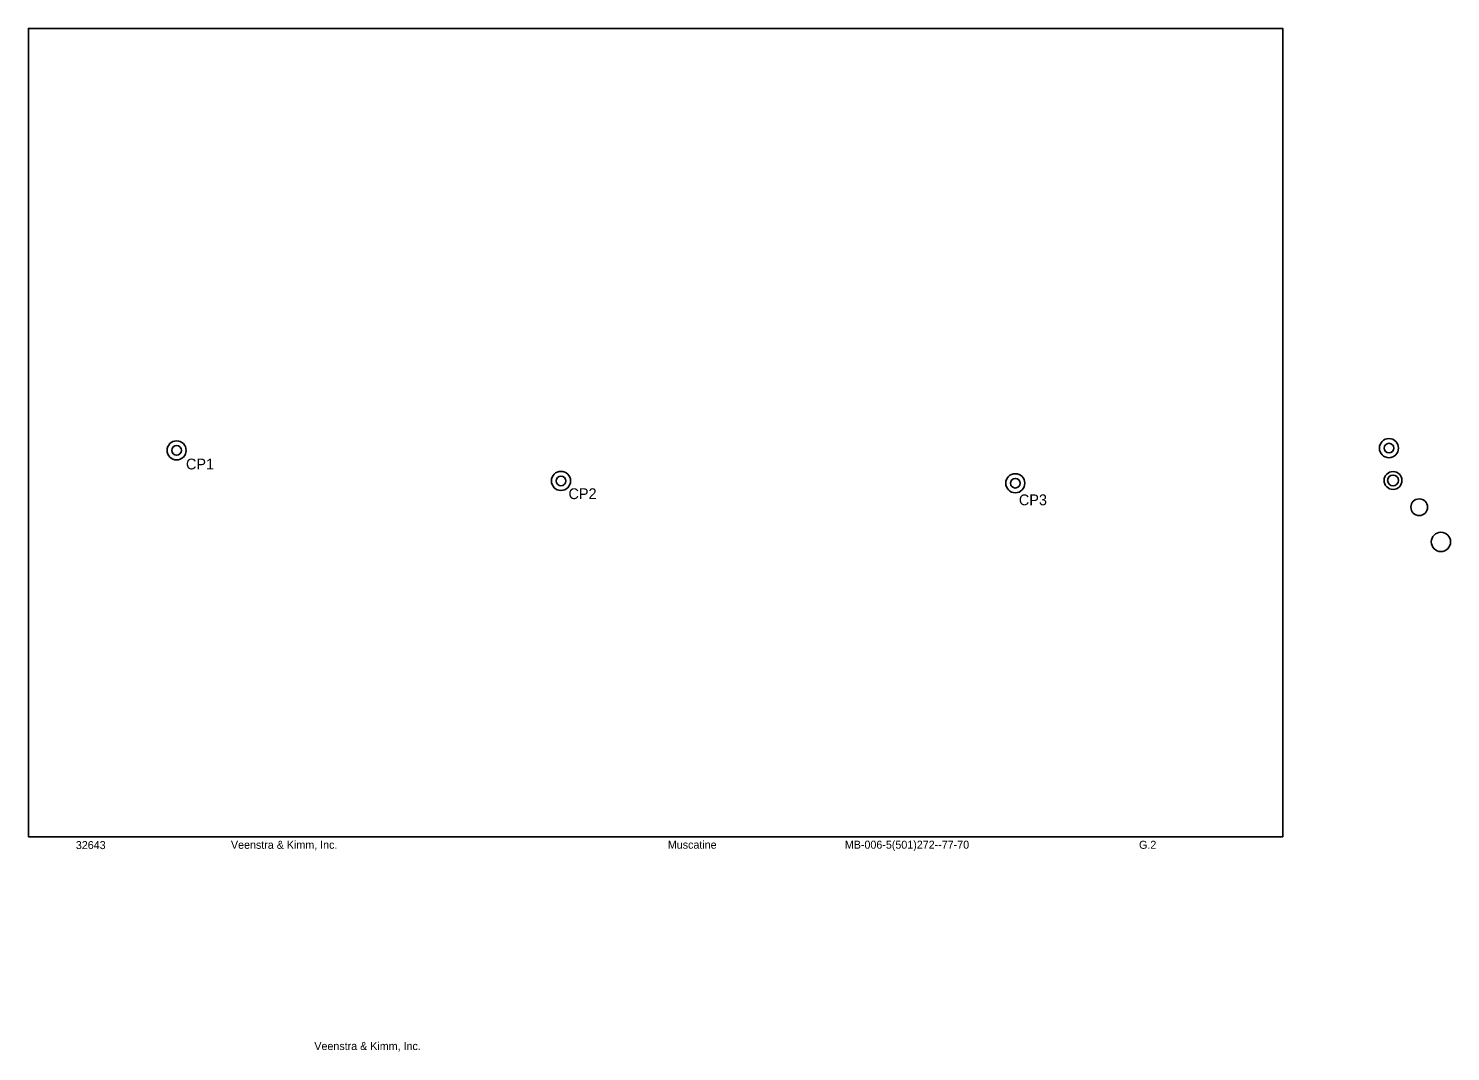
# Model space of a CAD drawing. Extents: x 0.11 to 3.07, y -0.34 to 1.79.
import ezdxf

# ---------------------------------------------------------------- set-up
doc = ezdxf.new("R2010")
doc.units = 0
for name, color, linetype in [('Building', 7, 'Continuous'), ('Default', 7, 'Continuous'), ('dsnCellElements', 7, 'Continuous'), ('SurUtilityPoleCell', 7, 'Continuous')]:
    doc.layers.add(name, color=color, linetype=linetype)

msp = doc.modelspace()

# ---------------------------------------------------------------- linework, layer by layer
at = {"layer": 'Default'}
msp.add_lwpolyline([(0.4187, 0.1033), (0.1104, 0.1033), (0.1104, 1.7867), (2.7229, 1.7867), (2.7229, 0.1033), (1.6658, 0.1033), (1.0606, 0.1033)], close=True, dxfattribs=at)
msp.add_circle((3.0523, 0.7174), 0.0201, dxfattribs=at)
at = {"layer": 'dsnCellElements'}
for centre, radius in [((0.419, 0.908), 0.0199), ((0.419, 0.908), 0.0199), ((2.9441, 0.9127), 0.0199), ((2.9441, 0.9127), 0.0199), ((2.9441, 0.9127), 0.01), ((2.9441, 0.9127), 0.01), ((0.419, 0.908), 0.01), ((0.419, 0.908), 0.01), ((1.2196, 0.8444), 0.0199), ((1.2196, 0.8444), 0.0199), ((2.1658, 0.8396), 0.0199), ((2.1658, 0.8396), 0.0199), ((2.1658, 0.8396), 0.0199), ((2.9526, 0.8454), 0.0186), ((2.9526, 0.8454), 0.0186), ((1.2196, 0.8444), 0.01), ((1.2196, 0.8444), 0.01), ((2.1658, 0.8396), 0.01), ((2.1658, 0.8396), 0.01), ((2.1658, 0.8396), 0.01), ((2.9526, 0.8454), 0.0113), ((2.9526, 0.8454), 0.0113), ((3.0071, 0.7896), 0.0174)]:
    msp.add_circle(centre, radius, dxfattribs=at)
for centre, radius, start, end in [((0.419, 0.908), 0.0199, 0, 180), ((2.9441, 0.9127), 0.0199, 0, 180), ((2.9441, 0.9127), 0.01, 0, 180), ((0.419, 0.908), 0.0199, 180, 0), ((0.419, 0.908), 0.01, 0, 180), ((0.419, 0.908), 0.01, 180, 0), ((2.9441, 0.9127), 0.0199, 180, 0), ((2.9441, 0.9127), 0.01, 180, 0), ((1.2196, 0.8444), 0.0199, 0, 180), ((2.1658, 0.8396), 0.0199, 0, 180), ((1.2196, 0.8444), 0.0199, 180, 0), ((1.2196, 0.8444), 0.01, 0, 180), ((1.2196, 0.8444), 0.01, 180, 0), ((2.1658, 0.8396), 0.0199, 180, 0), ((2.1658, 0.8396), 0.01, 0, 180), ((2.1658, 0.8396), 0.01, 180, 0)]:
    msp.add_arc(centre, radius, start, end, dxfattribs=at)

# ---------------------------------------------------------------- texts
at = {"layer": 'Building'}
for s, height, p in [('32643', 0.01667, (0.2092, 0.0777)), ('Veenstra & Kimm, Inc.', 0.016667, (0.5322, 0.0783)), ('Muscatine', 0.01667, (1.4421, 0.0785)), ('MB-006-5(501)272--77-70', 0.016667, (1.8108, 0.0785)), ('G.2', 0.01667, (2.4236, 0.0783)), ('Veenstra & Kimm, Inc.', 0.016667, (0.7059, -0.3408))]:
    msp.add_text(s, height=height, dxfattribs=at).set_placement(p)
at = {"layer": 'SurUtilityPoleCell'}
for s, p in [('CP1', (0.4385, 0.8683)), ('CP2', (1.2352, 0.8065)), ('CP3', (2.1733, 0.7937))]:
    msp.add_text(s, height=0.0225, dxfattribs=at).set_placement(p)

doc.saveas('drawing.dxf')
